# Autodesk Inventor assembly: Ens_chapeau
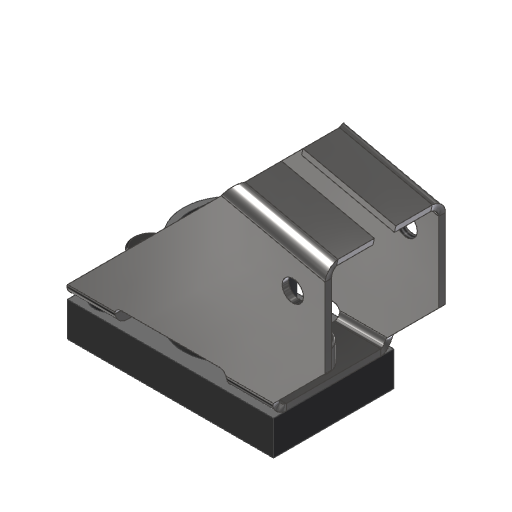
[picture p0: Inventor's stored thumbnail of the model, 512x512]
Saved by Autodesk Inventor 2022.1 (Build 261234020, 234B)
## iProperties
Created: 2018-06
Part Number: Ens_chapeau
Material: Générique
Document SubType Name: Assembly
Designer: Fabian Perrée
Mass: 105.136 g
Surface Area: 173.547 cm^2
Volume: 19.7524 cm^3
Density: 5.32267 g/cm^3
Author: Fabian Perrée
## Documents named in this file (5)
- C:\Users\fabia\Mon Drive\01_Giup\01_Clients\07_ENI\Manuscrit\Fichiers_exercice\Chapitre_06\Exercice_jeu_de_composant_en_contact\Composants\Ens_chapeau\Ens_chapeau.iam
- C:\Users\fabia\Mon Drive\01_Giup\01_Clients\07_ENI\Manuscrit\Fichiers_exercice\Chapitre_06\Exercice_jeu_de_composant_en_contact\Composants\Ens_chapeau\Composants\Chapeau_capteur.ipt
- C:\Users\fabia\Mon Drive\01_Giup\01_Clients\07_ENI\Manuscrit\Fichiers_exercice\Chapitre_06\Exercice_jeu_de_composant_en_contact\Composants\Ens_chapeau\Composants\Bille_18.ipt
- C:\Users\fabia\Mon Drive\01_Giup\01_Clients\07_ENI\Manuscrit\Fichiers_exercice\Chapitre_06\Exercice_jeu_de_composant_en_contact\Composants\Ens_levier\Composants\Etrier_tole.ipt
- C:\Users\fabia\Mon Drive\01_Giup\01_Clients\07_ENI\Manuscrit\Fichiers_exercice\CC\fr-FR\ISO 4762(2)\ISO 4762 - M5 x 8ISO.ipt
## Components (5 placed, 4 different names)
1. Etrier_tole:1 — Logement:3, Logement:4
2. Chapeau_capteur:1 — Logement:3, Logement:4
3. Bille_18:1
4. ISO 4762 M5 x 8:1
5. ISO 4762 M5 x 8:2
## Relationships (2: Insert 2)
- Logement:3 [Insert]: Etrier_tole:1 ↔ Chapeau_capteur:1
- Logement:4 [Insert]: Etrier_tole:1 ↔ Chapeau_capteur:1
